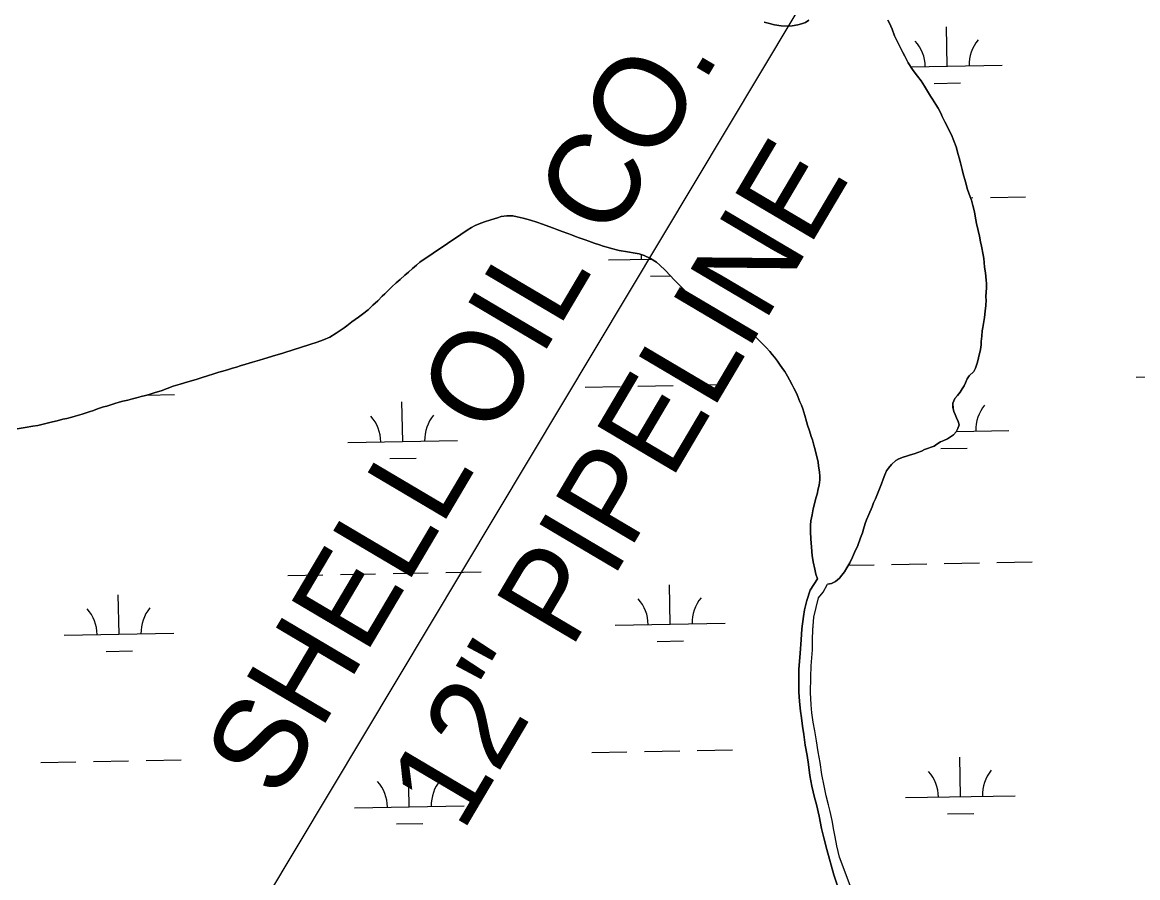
# Model space of a CAD drawing. Extents: x 3925854 to 3964121, y 224593 to 250589.
# Drawn here: x 3947792 to 3948807, y 238810 to 239589 of the extents above; entities that cross this region are included whole.
import ezdxf

# ---------------------------------------------------------------- set-up
doc = ezdxf.new("R2010")
doc.units = 0
for name, color, linetype in [('V-TOPO-SHOR', 7, 'Continuous'), ('V-UTIL-IDEN', 7, 'Continuous'), ('V-UTIL-LINE', 7, 'Continuous'), ('V-WETL-SWMP', 7, 'Continuous')]:
    doc.layers.add(name, color=color, linetype=linetype)

msp = doc.modelspace()

# ---------------------------------------------------------------- linework, layer by layer
at = {"layer": 'V-TOPO-SHOR'}
for points in [[(3948579.7, 239591.222), (3948581.085, 239588.385), (3948583.448, 239582.913), (3948585.805, 239576.937), (3948588.37, 239571.262), (3948591.239, 239565.886), (3948593.414, 239561.628), (3948595.196, 239558.282), (3948598.159, 239552.3), (3948602.232, 239546.305), (3948604.616, 239542.752), (3948606.607, 239540.208), (3948609.892, 239535.938), (3948612.968, 239531.166), (3948615.743, 239526.497), (3948618.522, 239522.03), (3948620.408, 239519.085), (3948623.487, 239514.414), (3948625.469, 239511.065), (3948627.841, 239506.402), (3948629.221, 239503.26), (3948631.49, 239498.497), (3948633.274, 239495.251), (3948635.945, 239490.18), (3948637.522, 239486.633), (3948639.785, 239481.162), (3948641.847, 239475.895), (3948643.793, 239468.915), (3948644.567, 239465.782), (3948645.73, 239461.229), (3948647.282, 239455.263), (3948648.149, 239451.319), (3948650.293, 239444.036), (3948652.236, 239437.057), (3948654.688, 239430.171), (3948655.765, 239427.134), (3948657.127, 239422.278), (3948658.479, 239416.515), (3948659.245, 239412.473), (3948660.387, 239405.905)], [(3948466.915, 239589.366), (3948470.737, 239588.32), (3948476.471, 239586.745), (3948482.515, 239586.079), (3948488.663, 239585.61), (3948492.601, 239585.975), (3948497.651, 239586.829), (3948501.092, 239587.802), (3948504.735, 239588.975), (3948507.682, 239591.062)], [(3948424.358, 239321.791), (3948421.445, 239323.032), (3948416.329, 239325.709), (3948413.724, 239327.45), (3948410.822, 239329.598), (3948406.925, 239333.067), (3948404.127, 239335.617), (3948401.332, 239338.37), (3948397.138, 239342.447), (3948394.043, 239345.607), (3948391.848, 239347.85), (3948388.855, 239351.008), (3948384.761, 239355.083), (3948381.87, 239358.241), (3948376.778, 239363.437), (3948372.086, 239368.025), (3948368.988, 239370.679), (3948363.577, 239374.165), (3948357.752, 239376.647), (3948353.228, 239378.205), (3948349.608, 239379.051), (3948342.659, 239380.233), (3948335.106, 239381.32), (3948328.065, 239383.106), (3948325.046, 239383.946), (3948320.321, 239385.406), (3948317.104, 239386.449), (3948312.281, 239388.114), (3948307.355, 239389.777), (3948303.937, 239390.921), (3948298.713, 239392.791), (3948295.196, 239394.241), (3948291.68, 239395.488), (3948288.264, 239396.734), (3948283.14, 239398.704), (3948278.317, 239400.57), (3948275.202, 239401.71), (3948271.083, 239403.267), (3948265.255, 239405.446), (3948260.028, 239407.213), (3948254.298, 239408.989), (3948247.457, 239410.873), (3948242.227, 239412.139), (3948238.299, 239412.786), (3948232.654, 239413.046), (3948227.702, 239412.19), (3948224.264, 239411.215), (3948218.294, 239409.362), (3948212.523, 239407.404), (3948207.562, 239405.64), (3948203.917, 239404.166), (3948200.468, 239402.384), (3948196.509, 239400.004), (3948190.82, 239395.929), (3948153.641, 239370.593), (3948150.384, 239368.004), (3948146.722, 239364.916), (3948143.059, 239361.727), (3948139.7, 239358.837), (3948135.624, 239354.944), (3948132.063, 239351.956), (3948128.092, 239348.366), (3948125.137, 239345.472), (3948121.671, 239341.976), (3948119.328, 239339.783), (3948115.15, 239335.591), (3948110.77, 239331.501), (3948106.391, 239327.411), (3948101.204, 239323.327), (3948097.546, 239320.745), (3948091.65, 239316.266), (3948086.972, 239312.684), (3948084.535, 239310.894), (3948081.08, 239308.508), (3948077.324, 239306.126), (3948071.436, 239302.556), (3948065.763, 239300.093), (3948060.09, 239297.932), (3948053.411, 239295.784), (3948050.477, 239294.905), (3948047.442, 239293.928), (3948042.887, 239292.361), (3948039.85, 239291.385), (3948035.397, 239289.918), (3948032.462, 239288.939), (3948027.807, 239287.577)], [(3948660.387, 239405.905), (3948661.833, 239399.636), (3948662.99, 239394.378), (3948664.148, 239389.324), (3948665.014, 239385.281), (3948666.445, 239377.398), (3948667.015, 239373.964), (3948667.383, 239370.529), (3948667.74, 239366.087), (3948668.496, 239361.037), (3948669.233, 239354.473), (3948669.503, 239351.344), (3948669.558, 239346.906), (3948669.223, 239343.68), (3948668.973, 239339.144), (3948669.042, 239336.017), (3948668.893, 239331.38), (3948668.334, 239326.139), (3948667.568, 239320.196), (3948667.025, 239316.571), (3948666.062, 239311.336), (3948665.626, 239308.215), (3948665.172, 239303.275), (3948664.719, 239298.44), (3948664.483, 239295.315), (3948663.937, 239291.186), (3948662.245, 239283.537), (3948661.297, 239279.713), (3948659.325, 239274.288), (3948657.881, 239271.277), (3948653.602, 239267.185), (3948651.858, 239264.38), (3948650.41, 239260.966), (3948649.068, 239257.953), (3948647.428, 239255.348), (3948645.378, 239252.241), (3948643.029, 239249.341), (3948640.778, 239246.439), (3948638.92, 239242.325), (3948638.683, 239238.796), (3948639.85, 239234.849), (3948641.032, 239232.013), (3948642.211, 239228.976), (3948643.688, 239225.531), (3948644.464, 239222.498), (3948643.522, 239219.178), (3948641.978, 239216.168), (3948639.328, 239213.573), (3948636.788, 239211.785), (3948634.044, 239209.794), (3948630.599, 239208.318), (3948627.56, 239207.138), (3948624.312, 239204.955), (3948621.768, 239203.062), (3948613.126, 239200.208)], [(3948515.575, 239082.2), (3948514.107, 239086.552), (3948513.044, 239091), (3948511.703, 239097.672), (3948510.754, 239103.632), (3948510.587, 239106.761), (3948510.029, 239111.406), (3948509.597, 239118.472), (3948509.368, 239125.333), (3948509.327, 239131.184), (3948509.669, 239135.014), (3948510.734, 239140.449), (3948511.598, 239145.987), (3948512.755, 239150.615), (3948514.222, 239155.846), (3948515.168, 239159.467), (3948516.327, 239164.396), (3948516.966, 239167.618), (3948517.621, 239172.351), (3948517.855, 239175.376), (3948517.494, 239179.715), (3948516.64, 239184.868), (3948516.077, 239188.808), (3948514.826, 239194.672), (3948513.28, 239201.144), (3948512.401, 239204.076), (3948511.039, 239208.832), (3948509.964, 239211.969), (3948508.401, 239217.13), (3948506.64, 239222.191), (3948505.567, 239225.734), (3948504.006, 239230.993), (3948502.155, 239237.065), (3948500.979, 239240.506), (3948499.599, 239243.648), (3948497.834, 239248.508), (3948496.453, 239251.446), (3948494.18, 239256.009), (3948492.597, 239258.95), (3948490.123, 239263.515), (3948488.341, 239266.761), (3948485.765, 239271.126), (3948483.876, 239273.968), (3948481.093, 239277.931), (3948479.305, 239280.673), (3948476.518, 239284.233), (3948474.427, 239286.777), (3948472.234, 239289.22), (3948468.842, 239292.986), (3948466.448, 239295.433), (3948462.755, 239299.204), (3948460.359, 239301.647), (3948456.462, 239305.016), (3948452.86, 239307.779), (3948447.355, 239311.971), (3948442.239, 239314.646), (3948438.122, 239316.505), (3948434.608, 239317.953), (3948431.29, 239319.198), (3948427.673, 239320.546), (3948424.358, 239321.791)], [(3948027.807, 239287.577), (3948024.469, 239286.703), (3948019.208, 239285.044), (3948014.352, 239283.582), (3948011.417, 239282.703), (3948007.571, 239281.431), (3948001.095, 239279.584), (3947995.025, 239277.831), (3947989.969, 239276.371), (3947986.425, 239275.195), (3947982.884, 239274.124), (3947979.344, 239273.051), (3947974.183, 239271.49), (3947970.439, 239270.419), (3947965.075, 239268.76), (3947961.028, 239267.39), (3947954.45, 239265.34), (3947949.797, 239263.976), (3947942.31, 239261.836), (3947935.228, 239259.69), (3947928.852, 239257.638), (3947917.916, 239253.615), (3947914.678, 239252.54), (3947911.44, 239251.565), (3947906.99, 239250.3), (3947903.752, 239249.425), (3947899.807, 239248.458), (3947895.459, 239247.291), (3947891.718, 239246.322), (3947887.569, 239245.155), (3947883.118, 239243.992), (3947879.782, 239243.22), (3947875.836, 239241.848), (3947872.901, 239240.971), (3947868.448, 239239.705), (3947865.516, 239238.829), (3947859.949, 239237.07), (3947856.304, 239235.695), (3947852.458, 239234.323), (3947846.082, 239232.371), (3947839.506, 239230.524), (3947836.473, 239229.648), (3947831.92, 239228.384), (3947828.482, 239227.614), (3947823.124, 239226.356), (3947818.977, 239225.189), (3947812.911, 239223.839), (3947809.167, 239222.871), (3947805.73, 239222.099), (3947801.184, 239221.238), (3947794.01, 239220.001), (3947786.735, 239218.967)], [(3948613.126, 239200.208), (3948610.185, 239198.725), (3948606.943, 239197.347), (3948603.605, 239196.271), (3948600.264, 239195.196), (3948596.623, 239194.125), (3948593.686, 239193.146), (3948589.637, 239191.676), (3948586.997, 239189.988), (3948583.127, 239186.398), (3948580.27, 239183.201), (3948578.529, 239180.696), (3948576.776, 239176.983), (3948575.424, 239173.164), (3948573.868, 239168.945), (3948572.727, 239165.83), (3948570.964, 239161.308), (3948569.52, 239158.095), (3948568.279, 239155.182), (3948566.726, 239151.467), (3948565.379, 239147.951), (3948562.28, 239141.024), (3948560.212, 239136.003), (3948558.968, 239132.787), (3948557.4, 239127.456), (3948556.46, 239124.239), (3948554.899, 239119.717), (3948552.206, 239112.785), (3948549.415, 239106.258), (3948547.555, 239102.041), (3948544.981, 239096.923), (3948542.308, 239092.311), (3948540.256, 239088.702), (3948537.802, 239085.599), (3948535.656, 239083.001), (3948532.093, 239079.81), (3948528.242, 239078.134), (3948524.808, 239077.465)], [(3948498.604, 238999.809), (3948499.767, 239014.614), (3948500.736, 239026.81), (3948501.346, 239036.906), (3948502.806, 239047.92), (3948503.881, 239054.138), (3948505.989, 239062.537), (3948508.864, 239071.935), (3948515.575, 239082.2)], [(3948512.268, 239047.312), (3948516.491, 239064.863), (3948520.839, 239070.123), (3948524.808, 239077.465)], [(3948545.431, 238803.121), (3948535.593, 238828.682), (3948533.258, 238838.977), (3948531.746, 238847.413), (3948530.546, 238853.401), (3948529.039, 238862.259), (3948527.27, 238870.275), (3948525.731, 238876.351), (3948523.544, 238884.625), (3948521.619, 238893.823), (3948519.538, 238904.116), (3948517.884, 238915.077), (3948516.298, 238924.69), (3948514.637, 238934.895), (3948513.214, 238943.835), (3948511.699, 238951.847), (3948510.353, 238960.112), (3948509.757, 238967.61), (3948509.2, 238978.731), (3948509.427, 238992.618), (3948509.872, 239003.055), (3948510.949, 239017.608), (3948511.049, 239027.289), (3948511.221, 239035.704), (3948512.268, 239047.312)], [(3948538.806, 238788.261), (3948530.421, 238812.66), (3948524.177, 238835.709), (3948521.511, 238846.43), (3948519.243, 238855.04), (3948517.003, 238866.261), (3948514.836, 238876.638), (3948512.884, 238883.14), (3948510.296, 238893.44), (3948508.631, 238903.307), (3948507.304, 238913.338), (3948506.126, 238921.434), (3948504.371, 238930.795), (3948503.038, 238940.409), (3948501.938, 238947.996), (3948500.924, 238955.836), (3948500.062, 238961.822), (3948499.14, 238970.504), (3948498.729, 238979.517), (3948498.573, 238988.778), (3948498.604, 238999.809)]]:
    msp.add_lwpolyline(points, dxfattribs=at)
at = {"layer": 'V-UTIL-LINE'}
msp.add_lwpolyline([(3951084.343, 243921.319), (3947981.77, 238738.296), (3948844.302, 237642.921), (3949260.796, 236134.673), (3945931.135, 235655.081), (3945509.058, 234777.685), (3942603.575, 230254.808)], dxfattribs=at)
at = {"layer": 'V-WETL-SWMP'}
for p, q in [((3948633.649, 239549.148), (3948632.994, 239585.142)), ((3948600.708, 239548.549), (3948683.641, 239550.057)), ((3948621.931, 239533.501), (3948645.928, 239533.937)), ((3948654.945, 239429.444), (3948656.984, 239429.481)), ((3948672.982, 239429.772), (3948704.976, 239430.354)), ((3948325.37, 239372.701), (3948364.738, 239373.417)), ((3948363.644, 239357.963), (3948381.817, 239358.294)), ((3948805.889, 239265.987), (3948837.884, 239266.569)), ((3948304.064, 239256.862), (3948336.059, 239257.444)), ((3948352.056, 239257.735), (3948384.051, 239258.317)), ((3948400.048, 239258.608), (3948432.043, 239259.189)), ((3947904.38, 239249.595), (3947930.218, 239250.065)), ((3948137.872, 239207.403), (3948137.217, 239243.397)), ((3948639.332, 239236.602), (3948639.216, 239242.98)), ((3948642.185, 239216.573), (3948689.689, 239217.437)), ((3948087.88, 239206.494), (3948187.864, 239208.312)), ((3948627.98, 239200.881), (3948651.976, 239201.317)), ((3948126.154, 239191.756), (3948150.151, 239192.193)), ((3948543.687, 239094.691), (3948567.048, 239095.116)), ((3948583.046, 239095.407), (3948615.04, 239095.988)), ((3948631.038, 239096.279), (3948663.032, 239096.861)), ((3948679.03, 239097.152), (3948711.024, 239097.734)), ((3948033.229, 239085.409), (3948065.223, 239085.991)), ((3948081.221, 239086.282), (3948113.215, 239086.864)), ((3948129.213, 239087.155), (3948161.207, 239087.736)), ((3948177.205, 239088.027), (3948209.199, 239088.609)), ((3948381.41, 239040.99), (3948380.755, 239076.984)), ((3947879.585, 239031.865), (3947878.93, 239067.859)), ((3947829.593, 239030.956), (3947929.576, 239032.774)), ((3948331.418, 239040.081), (3948431.401, 239041.899)), ((3948369.692, 239025.343), (3948393.688, 239025.78)), ((3947867.867, 239016.218), (3947891.863, 239016.655)), ((3948310.112, 238924.242), (3948342.107, 238924.824)), ((3948358.104, 238925.115), (3948390.099, 238925.697)), ((3948406.096, 238925.988), (3948438.091, 238926.569)), ((3947808.287, 238915.118), (3947840.282, 238915.699)), ((3947856.279, 238915.99), (3947888.274, 238916.572)), ((3947904.271, 238916.863), (3947936.266, 238917.445)), ((3948143.92, 238874.783), (3948143.266, 238910.777)), ((3948645.745, 238883.908), (3948645.091, 238919.902)), ((3948595.753, 238882.999), (3948695.737, 238884.817)), ((3948093.928, 238873.874), (3948193.912, 238875.692)), ((3948634.028, 238868.261), (3948658.024, 238868.697)), ((3948132.203, 238859.136), (3948156.199, 238859.572))]:
    msp.add_line(p, q, dxfattribs=at)
for points in [[(3948664.148, 239389.324), (3948662.99, 239394.379), (3948661.834, 239399.636), (3948660.387, 239405.905), (3948659.244, 239412.473), (3948658.479, 239416.515), (3948657.127, 239422.279), (3948655.765, 239427.134), (3948654.687, 239430.171), (3948652.237, 239437.056), (3948650.292, 239444.036), (3948648.149, 239451.32), (3948647.282, 239455.263), (3948645.73, 239461.23), (3948644.567, 239465.781), (3948643.792, 239468.916), (3948641.847, 239475.895), (3948639.784, 239481.162), (3948637.521, 239486.632), (3948635.944, 239490.179), (3948633.273, 239495.25), (3948631.491, 239498.496), (3948629.221, 239503.26), (3948627.841, 239506.401), (3948625.469, 239511.065), (3948623.486, 239514.414), (3948620.408, 239519.086), (3948618.522, 239522.031), (3948615.744, 239526.498), (3948612.968, 239531.166), (3948609.891, 239535.939), (3948606.607, 239540.209), (3948604.616, 239542.751), (3948602.232, 239546.306), (3948598.159, 239552.3), (3948595.195, 239558.281), (3948593.414, 239561.628), (3948591.239, 239565.887), (3948588.37, 239571.263), (3948585.806, 239576.938), (3948583.448, 239582.913), (3948581.084, 239588.385), (3948579.701, 239591.223)], [(3948507.682, 239591.062), (3948504.735, 239588.975), (3948501.092, 239587.802), (3948497.652, 239586.829), (3948492.6, 239585.974), (3948488.663, 239585.611), (3948482.515, 239586.079), (3948476.47, 239586.746), (3948470.737, 239588.319), (3948466.915, 239589.367)], [(3948050.477, 239294.906), (3948053.411, 239295.784), (3948060.091, 239297.933), (3948065.762, 239300.093), (3948071.436, 239302.556), (3948077.323, 239306.126), (3948081.079, 239308.508), (3948084.534, 239310.893), (3948086.973, 239312.683), (3948091.65, 239316.266), (3948097.546, 239320.744), (3948101.204, 239323.328), (3948106.391, 239327.41), (3948110.77, 239331.5), (3948115.15, 239335.59), (3948119.329, 239339.783), (3948121.672, 239341.977), (3948125.137, 239345.472), (3948128.092, 239348.366), (3948132.063, 239351.956), (3948135.625, 239354.945), (3948139.7, 239358.837), (3948143.058, 239361.727), (3948146.722, 239364.916), (3948150.385, 239368.005), (3948153.64, 239370.594), (3948190.819, 239395.929), (3948196.51, 239400.005), (3948200.468, 239402.385), (3948203.916, 239404.165), (3948207.563, 239405.64), (3948212.523, 239407.404), (3948218.293, 239409.361), (3948224.263, 239411.216), (3948227.703, 239412.189), (3948232.654, 239413.045), (3948238.299, 239412.785), (3948242.227, 239412.139), (3948247.458, 239410.874), (3948254.298, 239408.988), (3948260.028, 239407.214), (3948265.255, 239405.445), (3948271.083, 239403.266), (3948275.202, 239401.71), (3948278.317, 239400.569), (3948283.139, 239398.703), (3948288.263, 239396.733), (3948291.679, 239395.488), (3948295.196, 239394.241), (3948298.712, 239392.792), (3948303.937, 239390.922), (3948307.355, 239389.777), (3948312.28, 239388.113), (3948317.104, 239386.449), (3948320.321, 239385.407), (3948325.046, 239383.946), (3948328.064, 239383.107), (3948335.106, 239381.32), (3948342.659, 239380.233), (3948349.607, 239379.051), (3948353.229, 239378.206), (3948357.752, 239376.647), (3948363.576, 239374.165), (3948368.987, 239370.68), (3948372.086, 239368.025), (3948376.779, 239363.438), (3948381.869, 239358.241), (3948384.761, 239355.084), (3948388.855, 239351.007), (3948391.848, 239347.849), (3948394.043, 239345.607), (3948397.138, 239342.448), (3948401.332, 239338.37), (3948404.127, 239335.618), (3948406.925, 239333.067), (3948410.823, 239329.598), (3948413.725, 239327.449), (3948416.33, 239325.708), (3948421.446, 239323.032), (3948424.358, 239321.791), (3948427.674, 239320.547), (3948431.291, 239319.198), (3948434.607, 239317.953), (3948438.122, 239316.505), (3948442.238, 239314.646), (3948447.354, 239311.971), (3948452.859, 239307.778), (3948456.461, 239305.017), (3948460.36, 239301.648), (3948462.755, 239299.203), (3948466.448, 239295.433), (3948468.843, 239292.987), (3948472.234, 239289.22), (3948474.427, 239286.776), (3948476.519, 239284.233), (3948479.306, 239280.674), (3948481.094, 239277.932), (3948483.877, 239273.969), (3948485.764, 239271.126), (3948488.341, 239266.762), (3948490.123, 239263.516)], [(3948511.698, 238951.847), (3948510.353, 238960.112), (3948509.757, 238967.611), (3948509.199, 238978.73), (3948509.427, 238992.619), (3948509.872, 239003.054), (3948510.949, 239017.607), (3948511.049, 239027.288), (3948511.221, 239035.705), (3948512.267, 239047.312), (3948516.491, 239064.864), (3948520.839, 239070.123), (3948524.807, 239077.464), (3948528.243, 239078.135), (3948532.093, 239079.809), (3948535.656, 239083), (3948537.802, 239085.6), (3948540.255, 239088.702), (3948542.309, 239092.311), (3948544.98, 239096.923), (3948547.554, 239102.041), (3948549.414, 239106.258), (3948552.205, 239112.785), (3948554.899, 239119.717), (3948556.459, 239124.24), (3948557.4, 239127.457), (3948558.968, 239132.787), (3948560.212, 239136.002), (3948562.281, 239141.024), (3948565.379, 239147.951), (3948566.727, 239151.467), (3948568.278, 239155.183), (3948569.519, 239158.095), (3948570.964, 239161.308), (3948572.726, 239165.829), (3948573.868, 239168.944), (3948575.425, 239173.164), (3948576.775, 239176.983), (3948578.529, 239180.696), (3948580.269, 239183.2), (3948583.127, 239186.398), (3948586.997, 239189.989), (3948589.637, 239191.676), (3948593.687, 239193.147), (3948596.622, 239194.125), (3948600.264, 239195.197), (3948603.604, 239196.272), (3948606.943, 239197.347), (3948610.185, 239198.725), (3948613.126, 239200.208), (3948621.769, 239203.063), (3948624.311, 239204.954), (3948627.561, 239207.139), (3948630.599, 239208.318), (3948634.044, 239209.795), (3948636.788, 239211.784), (3948639.328, 239213.573), (3948641.977, 239216.168), (3948643.522, 239219.178), (3948644.464, 239222.497), (3948643.688, 239225.531), (3948642.211, 239228.975), (3948641.032, 239232.013), (3948639.851, 239234.85), (3948638.682, 239238.796), (3948638.92, 239242.324), (3948640.778, 239246.44), (3948643.028, 239249.341), (3948645.377, 239252.242), (3948647.427, 239255.348), (3948649.068, 239257.953), (3948650.41, 239260.965), (3948651.858, 239264.38), (3948653.602, 239267.186), (3948657.88, 239271.277), (3948659.324, 239274.288), (3948661.296, 239279.714), (3948662.244, 239283.537), (3948663.937, 239291.185), (3948664.484, 239295.315), (3948664.718, 239298.439), (3948665.172, 239303.276), (3948665.627, 239308.214), (3948666.063, 239311.336), (3948667.025, 239316.571), (3948667.567, 239320.196), (3948668.334, 239326.139), (3948668.893, 239331.379), (3948669.042, 239336.017), (3948668.973, 239339.144), (3948669.222, 239343.681), (3948669.558, 239346.905), (3948669.504, 239351.343), (3948669.233, 239354.473), (3948668.495, 239361.037), (3948667.74, 239366.088), (3948667.383, 239370.53), (3948667.015, 239373.963), (3948666.445, 239377.398), (3948665.014, 239385.281), (3948664.148, 239389.324)], [(3947786.736, 239218.968), (3947794.009, 239220.002), (3947801.183, 239221.239), (3947805.731, 239222.099), (3947809.168, 239222.871), (3947812.91, 239223.84), (3947818.976, 239225.19), (3947823.124, 239226.357), (3947828.482, 239227.613), (3947831.92, 239228.384), (3947836.472, 239229.648), (3947839.507, 239230.524), (3947846.082, 239232.372), (3947852.457, 239234.324), (3947856.304, 239235.696), (3947859.949, 239237.07), (3947865.515, 239238.828), (3947868.449, 239239.705), (3947872.901, 239240.97), (3947875.835, 239241.848), (3947879.783, 239243.219), (3947883.119, 239243.991), (3947887.569, 239245.155), (3947891.717, 239246.323), (3947895.459, 239247.292), (3947899.808, 239248.458), (3947903.752, 239249.425), (3947906.989, 239250.3), (3947911.44, 239251.565), (3947914.678, 239252.54), (3947917.916, 239253.616), (3947928.852, 239257.638), (3947935.227, 239259.69), (3947942.31, 239261.835), (3947949.796, 239263.977), (3947954.45, 239265.34), (3947961.028, 239267.39), (3947965.076, 239268.76), (3947970.439, 239270.419), (3947974.183, 239271.49), (3947979.343, 239273.05), (3947982.884, 239274.123), (3947986.426, 239275.196), (3947989.968, 239276.37), (3947995.026, 239277.83), (3948001.096, 239279.583), (3948007.571, 239281.432), (3948011.417, 239282.703), (3948014.351, 239283.581), (3948019.208, 239285.043), (3948024.47, 239286.703), (3948027.808, 239287.577), (3948032.462, 239288.94), (3948035.397, 239289.919), (3948039.85, 239291.385), (3948042.886, 239292.362), (3948047.441, 239293.929), (3948050.477, 239294.906)], [(3948490.123, 239263.516), (3948492.597, 239258.951), (3948494.18, 239256.009), (3948496.453, 239251.447), (3948497.834, 239248.508), (3948499.6, 239243.648), (3948500.979, 239240.507), (3948502.154, 239237.065), (3948504.007, 239230.994), (3948505.567, 239225.733), (3948506.639, 239222.191), (3948508.402, 239217.13), (3948509.963, 239211.97), (3948511.04, 239208.832), (3948512.402, 239204.077), (3948513.28, 239201.143), (3948514.826, 239194.671), (3948516.077, 239188.808), (3948516.641, 239184.869), (3948517.495, 239179.716), (3948517.854, 239175.375), (3948517.621, 239172.351), (3948516.967, 239167.618), (3948516.328, 239164.396), (3948515.167, 239159.466), (3948514.222, 239155.845), (3948512.756, 239150.615), (3948511.598, 239145.987), (3948510.734, 239140.449), (3948509.669, 239135.013), (3948509.326, 239131.184), (3948509.367, 239125.333), (3948509.598, 239118.472), (3948510.029, 239111.407), (3948510.586, 239106.762), (3948510.755, 239103.633), (3948511.702, 239097.672), (3948513.045, 239091.001), (3948514.108, 239086.552), (3948515.576, 239082.2), (3948508.865, 239071.936), (3948505.989, 239062.536), (3948503.881, 239054.139), (3948502.806, 239047.92), (3948501.345, 239036.907), (3948500.735, 239026.81), (3948499.767, 239014.613), (3948498.603, 238999.808), (3948498.573, 238988.779), (3948498.729, 238979.517), (3948499.141, 238970.504), (3948500.061, 238961.823), (3948500.925, 238955.836), (3948501.938, 238947.996), (3948503.038, 238940.408), (3948504.37, 238930.796), (3948506.125, 238921.433), (3948507.304, 238913.339), (3948508.631, 238903.306), (3948510.296, 238893.439), (3948512.884, 238883.141), (3948514.837, 238876.638), (3948517.002, 238866.26), (3948519.243, 238855.04), (3948521.511, 238846.429), (3948524.178, 238835.709), (3948530.422, 238812.661), (3948538.806, 238788.26)], [(3948545.431, 238803.121), (3948535.593, 238828.682), (3948533.258, 238838.978), (3948531.746, 238847.412), (3948530.546, 238853.402), (3948529.038, 238862.258), (3948527.269, 238870.274), (3948525.732, 238876.352), (3948523.545, 238884.625), (3948521.62, 238893.822), (3948519.538, 238904.115), (3948517.883, 238915.076), (3948516.299, 238924.69), (3948514.637, 238934.895), (3948513.215, 238943.834), (3948511.698, 238951.847)]]:
    msp.add_lwpolyline(points, dxfattribs=at)
for centre, start, end in [((3948578.407, 239548.618), 0.269879, 41.813537), ((3948688.874, 239550.627), 140.269876, 181.813534), ((3948320.119, 239373.08), 0.269879, 7.315915), ((3948694.922, 239218.007), 140.269876, 181.813534), ((3948082.63, 239206.873), 0.269879, 41.813537), ((3948193.097, 239208.882), 140.269876, 181.813534), ((3948326.167, 239040.46), 0.269879, 41.813537), ((3948436.635, 239042.469), 140.269876, 181.813534), ((3947824.342, 239031.336), 0.269879, 41.813537), ((3947934.81, 239033.344), 140.269876, 181.813534), ((3948590.503, 238883.378), 0.269879, 41.813537), ((3948700.97, 238885.387), 140.269876, 181.813534), ((3948088.678, 238874.253), 0.269879, 41.813537), ((3948199.145, 238876.262), 140.269876, 181.813534)]:
    msp.add_arc(centre, 35.246, start, end, dxfattribs=at)

# ---------------------------------------------------------------- texts
at = {"layer": 'V-UTIL-IDEN'}
for s, p in [('SHELL OIL CO.', (3948025.28, 238879.652)), ('12" PIPELINE', (3948192.425, 238850.573))]:
    msp.add_text(s, height=82.99983, rotation=59.393666, dxfattribs=at).set_placement(p)

doc.saveas('drawing.dxf')
